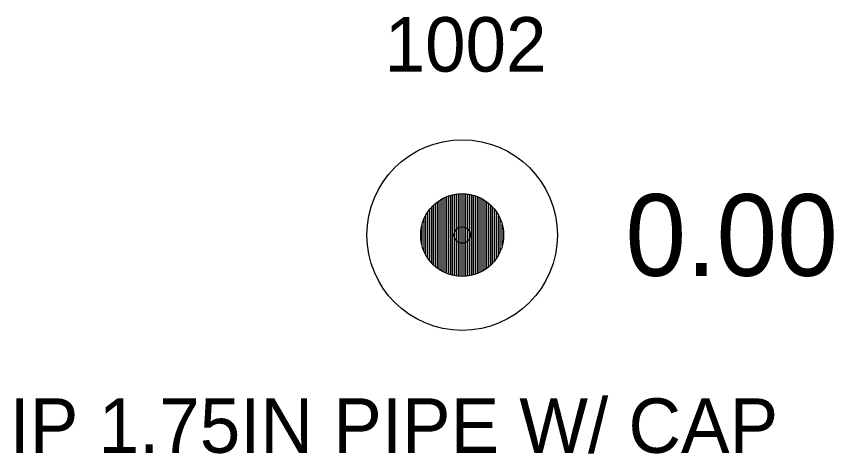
# Model space of a CAD drawing. Extents: x 1611865 to 1617004, y 775289 to 778546.
# Drawn here: x 1616452.43 to 1616467.45, y 775289.07 to 775297.1 of the extents above; entities that cross this region are included whole.
import ezdxf

# ---------------------------------------------------------------- set-up
doc = ezdxf.new("R2010")
doc.units = 0
for name, color, linetype in [('RD_EX_DV_Prop_txCode', 7, 'Continuous'), ('RD_EX_DV_PropPin', 7, 'Continuous'), ('RD_EX_TX_DV_Prop_ELEV', 7, 'Continuous'), ('RD_SMD_Locator', 7, 'Continuous')]:
    doc.layers.add(name, color=color, linetype=linetype)

msp = doc.modelspace()

# ---------------------------------------------------------------- linework, layer by layer
at = {"layer": 'RD_EX_DV_PropPin'}
for p, q in [((1616460.41, 775292.354), (1616460.41, 775293.817)), ((1616460.445, 775292.345), (1616460.445, 775293.826)), ((1616460.48, 775292.337), (1616460.48, 775293.834)), ((1616460.515, 775292.332), (1616460.515, 775293.839)), ((1616460.55, 775292.328), (1616460.55, 775293.843)), ((1616460.585, 775292.325), (1616460.585, 775293.846)), ((1616460.62, 775292.324), (1616460.62, 775293.847)), ((1616460.655, 775292.325), (1616460.655, 775293.846)), ((1616460.69, 775292.328), (1616460.69, 775293.843)), ((1616460.725, 775292.332), (1616460.725, 775293.839)), ((1616460.76, 775292.337), (1616460.76, 775293.834)), ((1616460.795, 775292.345), (1616460.795, 775293.826)), ((1616460.83, 775292.354), (1616460.83, 775293.817)), ((1616460.13, 775292.503), (1616460.13, 775293.668)), ((1616460.165, 775292.476), (1616460.165, 775293.695)), ((1616460.2, 775292.451), (1616460.2, 775293.72)), ((1616460.235, 775292.429), (1616460.235, 775293.742)), ((1616460.27, 775292.41), (1616460.27, 775293.761)), ((1616460.305, 775292.393), (1616460.305, 775293.778)), ((1616460.34, 775292.378), (1616460.34, 775293.793)), ((1616460.375, 775292.365), (1616460.375, 775293.806)), ((1616460.865, 775292.365), (1616460.865, 775293.806)), ((1616460.9, 775292.378), (1616460.9, 775293.793)), ((1616460.935, 775292.393), (1616460.935, 775293.778)), ((1616460.97, 775292.41), (1616460.97, 775293.761)), ((1616461.005, 775292.429), (1616461.005, 775293.742)), ((1616461.04, 775292.451), (1616461.04, 775293.72)), ((1616461.075, 775292.476), (1616461.075, 775293.695)), ((1616461.11, 775292.503), (1616461.11, 775293.668)), ((1616460.025, 775292.611), (1616460.025, 775293.56)), ((1616460.06, 775292.57), (1616460.06, 775293.601)), ((1616460.095, 775292.535), (1616460.095, 775293.636)), ((1616461.145, 775292.535), (1616461.145, 775293.636)), ((1616461.18, 775292.57), (1616461.18, 775293.601)), ((1616461.215, 775292.611), (1616461.215, 775293.56)), ((1616459.92, 775292.788), (1616459.92, 775293.383)), ((1616459.955, 775292.716), (1616459.955, 775293.455)), ((1616459.99, 775292.659), (1616459.99, 775293.512)), ((1616461.25, 775292.659), (1616461.25, 775293.512)), ((1616461.285, 775292.716), (1616461.285, 775293.455)), ((1616461.32, 775292.788), (1616461.32, 775293.383)), ((1616459.885, 775292.889), (1616459.885, 775293.282)), ((1616461.355, 775292.889), (1616461.355, 775293.282))]:
    msp.add_line(p, q, dxfattribs=at)
for radius in [1.75, 0.761]:
    msp.add_circle((1616460.62, 775293.085), radius, dxfattribs=at)
at = {"layer": 'RD_SMD_Locator'}
msp.add_circle((1616460.62, 775293.085), 0.15, dxfattribs=at)

# ---------------------------------------------------------------- texts
at = {"layer": 'RD_EX_DV_Prop_txCode'}
for s, p in [('1002', (1616459.195, 775296.086)), ('IP 1.75IN PIPE W/ CAP', (1616452.305, 775289.086))]:
    msp.add_text(s, height=1, dxfattribs=at).set_placement(p)
at = {"layer": 'RD_EX_TX_DV_Prop_ELEV'}
msp.add_text('0.00', height=1.5, dxfattribs=at).set_placement((1616463.62, 775292.336))

doc.saveas('drawing.dxf')
